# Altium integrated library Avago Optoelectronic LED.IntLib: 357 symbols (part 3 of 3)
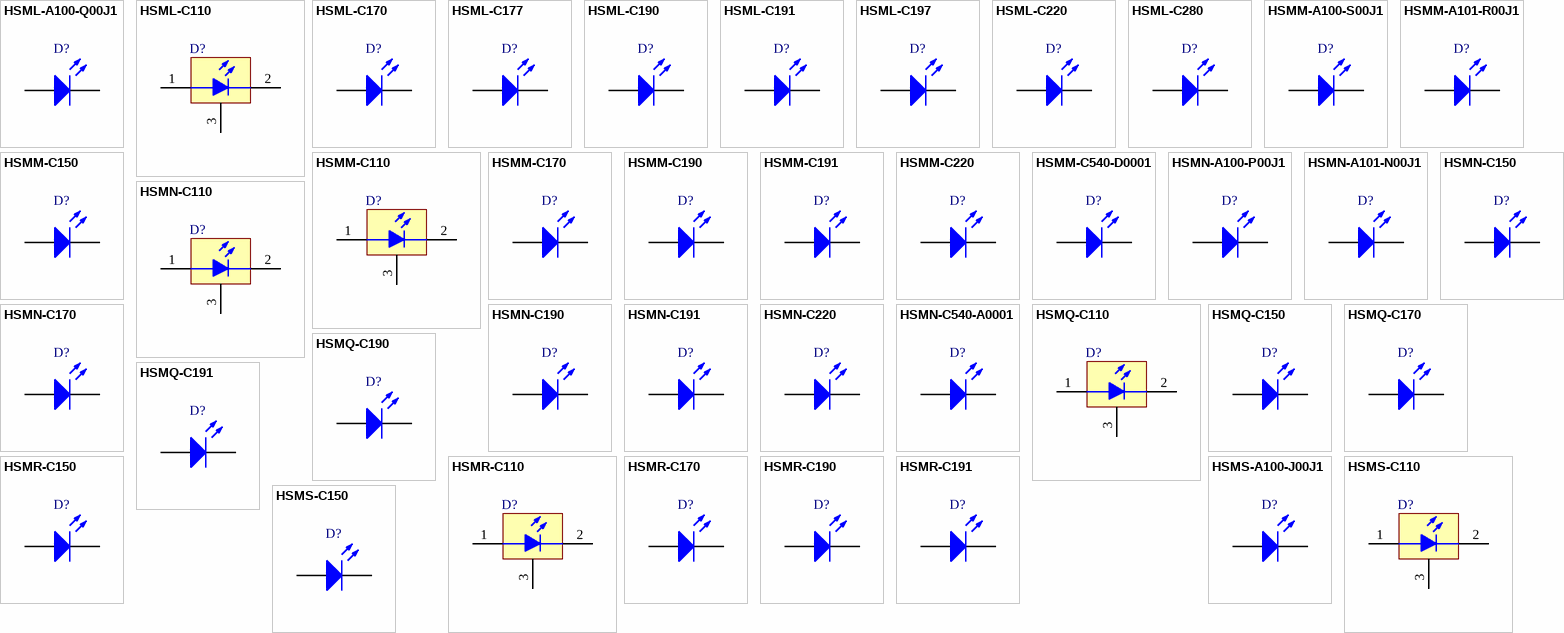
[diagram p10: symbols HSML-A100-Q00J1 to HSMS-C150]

## HSMN-A101-N00J1
designator D?
Surface Mount LED Indicator, Blue; LuminousIntensity: 25mcd (Minimum).; PCB_Layout: Complies with manufacturer's recommendation.
footprint 3.5X2.8X1.9 (SM LED; 2 C-Bend Leads; Body 3.5 x 2.8 x 1.9 mm, inc leads (LxWxH typ))
simulation model Agl_HSMKA100 (Diode)
signal-integrity model LED
pins: 1 A, 2 K

## HSMN-C110
designator D?
High Performance SMT Chip LED, Blue; LuminousIntensity: 10mcd (Minimum).; PCB_Layout: Complies with manufacturer's recommendation.
footprint 3.2X1.0X1.5 (SM Right-Angle Mount LED; 3 Leads; Body 3.2 x 1.0 x 1.5 mm (LxWxH))
simulation model Agl_HSMMC110 (Diode)
pins: 1 A, 2 K, 3 Mount

## HSMN-C150
designator D?
High Performance SMT Chip LED, Blue; LuminousIntensity: 10mcd (Minimum).; PCB_Layout: Complies with manufacturer's recommendation.
footprint 3.2X1.6X1.1 (SM LED; 2 Flat Leads)
simulation model Agl_HSMMC110 (Diode)
signal-integrity model LED
pins: 1 A, 2 K

## HSMN-C170
designator D?
High Performance SMT Chip LED, Blue; LuminousIntensity: 10mcd (Minimum).; PCB_Layout: Complies with manufacturer's recommendation.
footprint 2.0X1.25X0.8 (SM LED; 2 Flat Leads)
simulation model Agl_HSMMC110 (Diode)
signal-integrity model LED
pins: 1 A, 2 K

## HSMN-C190
designator D?
High Performance SMT Chip LED, Blue; LuminousIntensity: 10mcd (Minimum).; PCB_Layout: Complies with manufacturer's recommendation.
footprint 1.6X0.8X0.8 (SM LED; 2 Flat Leads)
simulation model Agl_HSMMC110 (Diode)
signal-integrity model LED
pins: 1 A, 2 K

## HSMN-C191
designator D?
High Performance SMT Chip LED, Blue; LuminousIntensity: 10mcd (Minimum).; PCB_Layout: Complies with manufacturer's recommendation.
footprint 1.6X0.8X0.6 (SM LED; 2 Flat Leads)
simulation model Agl_HSMMC110 (Diode)
signal-integrity model LED
pins: 1 A, 2 K

## HSMN-C220
designator D?
High Performance Chip LED, Blue; LuminousIntensity: 25mcd (Minimum).; PCB_Layout: Complies with manufacturer's recommendation.
footprint 2.0X1.25X1.2 (SM LED; 2 Flat Leads)
simulation model Agl_HSMNC220 (Diode)
signal-integrity model LED
pins: 1 A, 2 K

## HSMN-C540-A0001
designator D?
Top Mount InGaN Blue Oval Lens High Brightness; LuminousIntensity: 26mcd (Minimum).; PCB_Layout: Complies with manufacturer's recommendation.
footprint 2.0X1.25X1.2 (SM LED; 2 Flat Leads)
simulation model Agl_HSMMC540 (Diode)
signal-integrity model LED
pins: 1 A, 2 K

## HSMQ-C110
designator D?
Right Angle SMT Chip LED, Green; LuminousIntensity: 40mcd (Minimum).; PCB_Layout: Complies with manufacturer's recommendation.
footprint 3.2X1.0X1.5 (SM Right-Angle Mount LED; 3 Leads; Body 3.2 x 1.0 x 1.5 mm (LxWxH))
simulation model Agl_HSMQC110 (Diode)
pins: 1 A, 2 K, 3 Mount

## HSMQ-C150
designator D?
SMT Top Mount Chip LED, Green; LuminousIntensity: 40mcd (Minimum).; PCB_Layout: Complies with manufacturer's recommendation.
footprint 3.2X1.6X1.1 (SM LED; 2 Flat Leads)
simulation model Agl_HSMQC110 (Diode)
signal-integrity model LED
pins: 1 A, 2 K

## HSMQ-C170
designator D?
SMT Top Mount Chip LED, Green; LuminousIntensity: 40mcd (Minimum).; PCB_Layout: Complies with manufacturer's recommendation.
footprint 2.0X1.25X0.8 (SM LED; 2 Flat Leads)
simulation model Agl_HSMQC170 (Diode)
signal-integrity model LED
pins: 1 A, 2 K

## HSMQ-C190
designator D?
SMT Top Mount Chip LED, Green; LuminousIntensity: 40mcd (Minimum).; PCB_Layout: Complies with manufacturer's recommendation.
footprint 1.6X0.8X0.8 (SM LED; 2 Flat Leads)
simulation model Agl_HSMQC170 (Diode)
signal-integrity model LED
pins: 1 A, 2 K

## HSMQ-C191
designator D?
Top Mount Low Profile Chip LED, Green; LuminousIntensity: 40mcd (Minimum).; PCB_Layout: Complies with manufacturer's recommendation.
footprint 1.6X0.8X0.6 (SM LED; 2 Flat Leads)
simulation model Agl_HSMQC170 (Diode)
signal-integrity model LED
pins: 1 A, 2 K

## HSMR-C110
designator D?
Right Angle SMT Chip LED, Blue; LuminousIntensity: 16mcd (Minimum).; PCB_Layout: Complies with manufacturer's recommendation.
footprint 3.2X1.0X1.5 (SM Right-Angle Mount LED; 3 Leads; Body 3.2 x 1.0 x 1.5 mm (LxWxH))
simulation model Agl_HSMQC110 (Diode)
pins: 1 A, 2 K, 3 Mount

## HSMR-C150
designator D?
SMT Top Mount Chip LED, Blue; LuminousIntensity: 16mcd (Minimum).; PCB_Layout: Complies with manufacturer's recommendation.
footprint 3.2X1.6X1.1 (SM LED; 2 Flat Leads)
simulation model Agl_HSMQC110 (Diode)
signal-integrity model LED
pins: 1 A, 2 K

## HSMR-C170
designator D?
SMT Top Mount Chip LED, Blue; LuminousIntensity: 16mcd (Minimum).; PCB_Layout: Complies with manufacturer's recommendation.
footprint 2.0X1.25X0.8 (SM LED; 2 Flat Leads)
simulation model Agl_HSMQC170 (Diode)
signal-integrity model LED
pins: 1 A, 2 K

## HSMR-C190
designator D?
SMT Top Mount Chip LED, Blue; LuminousIntensity: 16mcd (Minimum).; PCB_Layout: Complies with manufacturer's recommendation.
footprint 1.6X0.8X0.8 (SM LED; 2 Flat Leads)
simulation model Agl_HSMQC170 (Diode)
signal-integrity model LED
pins: 1 A, 2 K

## HSMR-C191
designator D?
Top Mount Low Profile Chip LED, Blue; LuminousIntensity: 16mcd (Minimum).; PCB_Layout: Complies with manufacturer's recommendation.
footprint 1.6X0.8X0.6 (SM LED; 2 Flat Leads)
simulation model Agl_HSMQC170 (Diode)
signal-integrity model LED
pins: 1 A, 2 K

## HSMS-A100-J00J1
designator D?
Surface Mount LED Indicator, Red; LuminousIntensity: 4mcd (Minimum).; PCB_Layout: Complies with manufacturer's recommendation.
footprint 3.5X2.8X1.9 (SM LED; 2 C-Bend Leads; Body 3.5 x 2.8 x 1.9 mm, inc leads (LxWxH typ))
simulation model Agl_HSMDC110 (Diode)
signal-integrity model LED
pins: 1 A, 2 K

## HSMS-C110
designator D?
Surface Mount Chip LED, Red; LuminousIntensity: 2.5mcd (Minimum).; PCB_Layout: Complies with manufacturer's recommendation.
footprint 3.2X1.0X1.5 (SM Right-Angle Mount LED; 3 Leads; Body 3.2 x 1.0 x 1.5 mm (LxWxH))
simulation model Agl_HSMSC110 (Diode)
pins: 1 A, 2 K, 3 Mount

## HSMS-C150
designator D?
Surface Mount Chip LED, Red; LuminousIntensity: 2.5mcd (Minimum).; PCB_Layout: Complies with manufacturer's recommendation.
footprint 3.2X1.6X1.1 (SM LED; 2 Flat Leads)
simulation model Agl_HSMSC110 (Diode)
signal-integrity model LED
pins: 1 A, 2 K

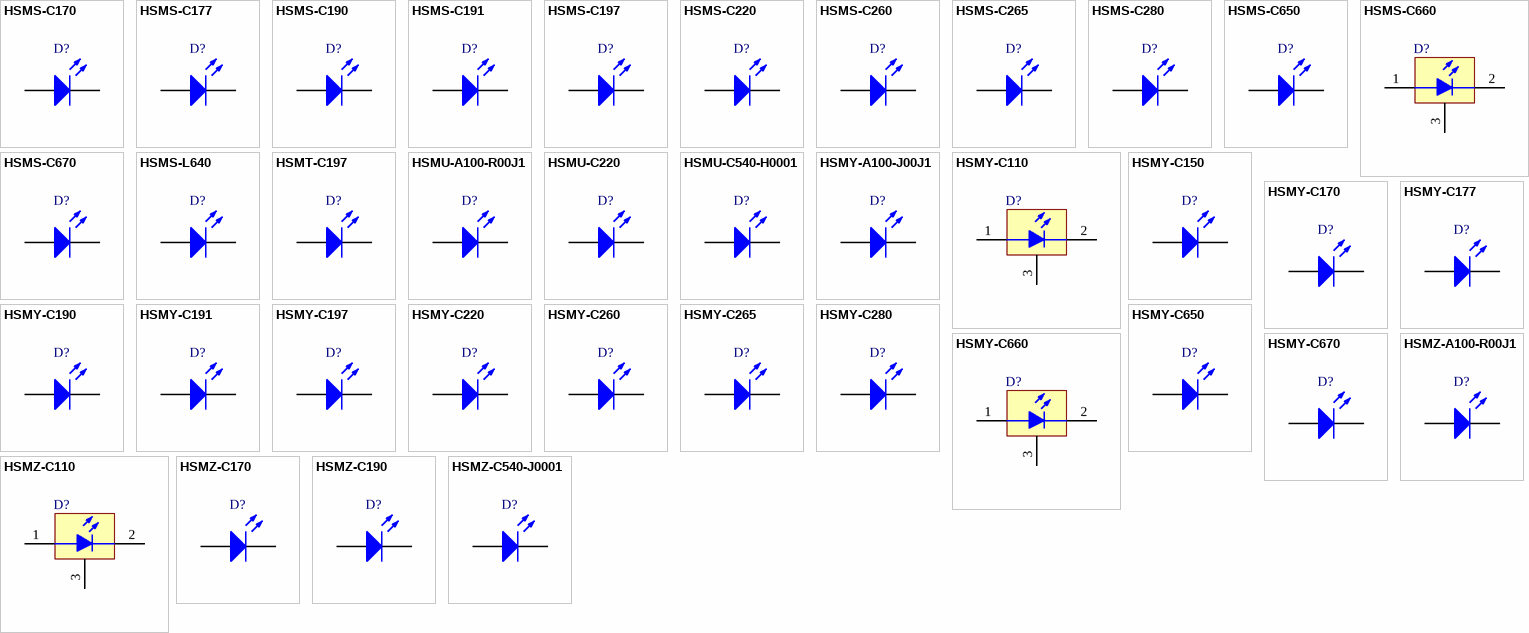
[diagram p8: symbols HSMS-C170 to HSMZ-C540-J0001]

## HSMS-C170
designator D?
Surface Mount Chip LED, Red; LuminousIntensity: 2.5mcd (Minimum).; PCB_Layout: Complies with manufacturer's recommendation.
footprint 2.0X1.25X0.8 (SM LED; 2 Flat Leads)
simulation model Agl_HSMSC110 (Diode)
signal-integrity model LED
pins: 1 A, 2 K

## HSMS-C177
designator D?
Low Profile Chip LED, Red; LuminousIntensity: 2.5mcd (Minimum).; PCB_Layout: Complies with manufacturer's recommendation.
footprint 2.0X1.25X0.4 (SM LED; 2 Flat Leads)
simulation model Agl_HSMSC110 (Diode)
signal-integrity model LED
pins: 1 A, 2 K

## HSMS-C190
designator D?
Surface Mount Chip LED, Red; LuminousIntensity: 2.5mcd (Minimum).; PCB_Layout: Complies with manufacturer's recommendation.
footprint 1.6X0.8X0.8 (SM LED; 2 Flat Leads)
simulation model Agl_HSMSC110 (Diode)
signal-integrity model LED
pins: 1 A, 2 K

## HSMS-C191
designator D?
Low Profile Chip LED, Red; LuminousIntensity: 2.5mcd (Minimum).; PCB_Layout: Complies with manufacturer's recommendation.
footprint 1.6X0.8X0.6 (SM LED; 2 Flat Leads)
simulation model Agl_HSMSC110 (Diode)
signal-integrity model LED
pins: 1 A, 2 K

## HSMS-C197
designator D?
Low Profile Chip LED, Red; LuminousIntensity: 2.5mcd (Minimum).; PCB_Layout: Complies with manufacturer's recommendation.
footprint 1.6X0.8X0.4 (SM LED; 2 Flat Leads)
simulation model Agl_HSMSC110 (Diode)
signal-integrity model LED
pins: 1 A, 2 K

## HSMS-C220
designator D?
High Performance Chip LED, Red; LuminousIntensity: 6.3mcd (Minimum).; PCB_Layout: Complies with manufacturer's recommendation.
footprint 2.0X1.25X1.2 (SM LED; 2 Flat Leads)
simulation model Agl_HSMDC650 (Diode)
signal-integrity model LED
pins: 1 A, 2 K

## HSMS-C260
designator D?
Reverse Mount Chip LED, Red; LuminousIntensity: 2.5mcd (Minimum).; PCB_Layout: Complies with manufacturer's recommendation.; DrillSize: Nominal, Rounded to nearest 0.05mm
footprint 3.4X1.25X1.1 (SM Reverse Mount LED; 2 Flat Leads)
simulation model Agl_HSMSC260 (Diode)
signal-integrity model LED
pins: 1 A, 2 K

## HSMS-C265
designator D?
Reverse Mount Chip LED, Red; LuminousIntensity: 2.5mcd (Minimum).; PCB_Layout: Complies with manufacturer's recommendation.; DrillSize: Nominal, Rounded to nearest 0.05mm
footprint 3.4X1.25X1.1 (SM Reverse Mount LED; 2 Flat Leads)
simulation model Agl_HSMSC265 (Diode)
signal-integrity model LED
pins: 1 A, 2 K

## HSMS-C280
designator D?
Miniature Chip LED, Red; LuminousIntensity: 2.5mcd (Minimum).; PCB_Layout: Complies with manufacturer's recommendation.
footprint 1.0X0.5X0.4 (SM LED; 2 Flat Leads)
simulation model Agl_HSMSC110 (Diode)
signal-integrity model LED
pins: 1 A, 2 K

## HSMS-C650
designator D?
SMT Top Mount Chip LED, Red; LuminousIntensity: 1.6mcd (Minimum).; PCB_Layout: Complies with manufacturer's recommendation.
footprint 3.2X1.6X1.1 (SM LED; 2 Flat Leads)
simulation model Agl_HSMSC650 (Diode)
signal-integrity model LED
pins: 1 A, 2 K

## HSMS-C660
designator D?
Right Angle SMT Chip LED, Red; LuminousIntensity: 1.6mcd (Minimum).; PCB_Layout: Complies with manufacturer's recommendation.
footprint 3.0X1.0X2.0W (SM Right-Angle Mount LED; 3 Leads; Body 3.0 x 1.0 x 2.0 mm (LxWxH))
simulation model Agl_HSMSC650 (Diode)
pins: 1 A, 2 K, 3 Mount

## HSMS-C670
designator D?
SMT Top Mount Chip LED, Red; LuminousIntensity: 1.6mcd (Minimum).; PCB_Layout: Complies with manufacturer's recommendation.
footprint 2.0X1.25X1.1 (SM LED; 2 Flat Leads)
simulation model Agl_HSMSC650 (Diode)
signal-integrity model LED
pins: 1 A, 2 K

## HSMS-L640
designator D?
SMT Top Mount Chip LED, Red; LuminousIntensity: 2.5mcd (Minimum).; PCB_Layout: Complies with manufacturer's recommendation.
footprint 3.0X1.5X1.5 (SM LED; 2 Flat Leads)
simulation model Agl_HSMSC650 (Diode)
signal-integrity model LED
pins: 1 A, 2 K

## HSMT-C197
designator D?
Low Profile Chip LED, Red; LuminousIntensity: 15mcd (Minimum).; PCB_Layout: Complies with manufacturer's recommendation.
footprint 1.6X0.8X0.4 (SM LED; 2 Flat Leads)
simulation model Agl_HSMCC177 (Diode)
signal-integrity model LED
pins: 1 A, 2 K

## HSMU-A100-R00J1
designator D?
Surface Mount LED Indicator, Amber; LuminousIntensity: 100mcd (Minimum).; PCB_Layout: Complies with manufacturer's recommendation.
footprint 3.5X2.8X1.9 (SM LED; 2 C-Bend Leads; Body 3.5 x 2.8 x 1.9 mm, inc leads (LxWxH typ))
simulation model Agl_HSMDC110 (Diode)
signal-integrity model LED
pins: 1 A, 2 K

## HSMU-C220
designator D?
High Performance Chip LED, Amber; LuminousIntensity: 100mcd (Minimum).; PCB_Layout: Complies with manufacturer's recommendation.
footprint 2.0X1.25X1.2 (SM LED; 2 Flat Leads)
simulation model Agl_HSMUC220 (Diode)
signal-integrity model LED
pins: 1 A, 2 K

## HSMU-C540-H0001
designator D?
Top Mount TS AlInGaP Amber Oval Lens High Brightness; LuminousIntensity: 157mcd (Minimum).; PCB_Layout: Complies with manufacturer's recommendation.
footprint 2.0X1.25X1.2 (SM LED; 2 Flat Leads)
simulation model Agl_HSMUC540 (Diode)
signal-integrity model LED
pins: 1 A, 2 K

## HSMY-A100-J00J1
designator D?
Surface Mount LED Indicator, Yellow; LuminousIntensity: 4mcd (Minimum).; PCB_Layout: Complies with manufacturer's recommendation.
footprint 3.5X2.8X1.9 (SM LED; 2 C-Bend Leads; Body 3.5 x 2.8 x 1.9 mm, inc leads (LxWxH typ))
simulation model Agl_HSMDC110 (Diode)
signal-integrity model LED
pins: 1 A, 2 K

## HSMY-C110
designator D?
Surface Mount Chip LED, Yellow; LuminousIntensity: 2.5mcd (Minimum).; PCB_Layout: Complies with manufacturer's recommendation.
footprint 3.2X1.0X1.5 (SM Right-Angle Mount LED; 3 Leads; Body 3.2 x 1.0 x 1.5 mm (LxWxH))
simulation model Agl_HSMYC110 (Diode)
pins: 1 A, 2 K, 3 Mount

## HSMY-C150
designator D?
Surface Mount Chip LED, Yellow; LuminousIntensity: 2.5mcd (Minimum).; PCB_Layout: Complies with manufacturer's recommendation.
footprint 3.2X1.6X1.1 (SM LED; 2 Flat Leads)
simulation model Agl_HSMYC110 (Diode)
signal-integrity model LED
pins: 1 A, 2 K

## HSMY-C170
designator D?
Surface Mount Chip LED, Yellow; LuminousIntensity: 2.5mcd (Minimum).; PCB_Layout: Complies with manufacturer's recommendation.
footprint 2.0X1.25X0.8 (SM LED; 2 Flat Leads)
simulation model Agl_HSMYC110 (Diode)
signal-integrity model LED
pins: 1 A, 2 K

## HSMY-C177
designator D?
Low Profile Chip LED, Yellow; LuminousIntensity: 2.5mcd (Minimum).; PCB_Layout: Complies with manufacturer's recommendation.
footprint 2.0X1.25X0.4 (SM LED; 2 Flat Leads)
simulation model Agl_HSMYC110 (Diode)
signal-integrity model LED
pins: 1 A, 2 K

## HSMY-C190
designator D?
Surface Mount Chip LED, Yellow; LuminousIntensity: 2.5mcd (Minimum).; PCB_Layout: Complies with manufacturer's recommendation.
footprint 1.6X0.8X0.8 (SM LED; 2 Flat Leads)
simulation model Agl_HSMYC110 (Diode)
signal-integrity model LED
pins: 1 A, 2 K

## HSMY-C191
designator D?
Low Profile Chip LED, Yellow; LuminousIntensity: 2.5mcd (Minimum).; PCB_Layout: Complies with manufacturer's recommendation.
footprint 1.6X0.8X0.6 (SM LED; 2 Flat Leads)
simulation model Agl_HSMYC110 (Diode)
signal-integrity model LED
pins: 1 A, 2 K

## HSMY-C197
designator D?
Low Profile Chip LED, Yellow; LuminousIntensity: 2.5mcd (Minimum).; PCB_Layout: Complies with manufacturer's recommendation.
footprint 1.6X0.8X0.4 (SM LED; 2 Flat Leads)
simulation model Agl_HSMYC110 (Diode)
signal-integrity model LED
pins: 1 A, 2 K

## HSMY-C220
designator D?
High Performance Chip LED, Yellow; LuminousIntensity: 6.3mcd (Minimum).; PCB_Layout: Complies with manufacturer's recommendation.
footprint 2.0X1.25X1.2 (SM LED; 2 Flat Leads)
simulation model Agl_HSMYC650 (Diode)
signal-integrity model LED
pins: 1 A, 2 K

## HSMY-C260
designator D?
Reverse Mount Chip LED, Yellow; LuminousIntensity: 2.5mcd (Minimum).; PCB_Layout: Complies with manufacturer's recommendation.; DrillSize: Nominal, Rounded to nearest 0.05mm
footprint 3.4X1.25X1.1 (SM Reverse Mount LED; 2 Flat Leads)
simulation model Agl_HSMYC260 (Diode)
signal-integrity model LED
pins: 1 A, 2 K

## HSMY-C265
designator D?
Reverse Mount Chip LED, Yellow; LuminousIntensity: 2.5mcd (Minimum).; PCB_Layout: Complies with manufacturer's recommendation.; DrillSize: Nominal, Rounded to nearest 0.05mm
footprint 3.4X1.25X1.1 (SM Reverse Mount LED; 2 Flat Leads)
simulation model Agl_HSMYC260 (Diode)
signal-integrity model LED
pins: 1 A, 2 K

## HSMY-C280
designator D?
Miniature Chip LED, Yellow; LuminousIntensity: 2.5mcd (Minimum).; PCB_Layout: Complies with manufacturer's recommendation.
footprint 1.0X0.5X0.4 (SM LED; 2 Flat Leads)
simulation model Agl_HSMYC110 (Diode)
signal-integrity model LED
pins: 1 A, 2 K

## HSMY-C650
designator D?
SMT Top Mount Chip LED, Yellow; LuminousIntensity: 1.6mcd (Minimum).; PCB_Layout: Complies with manufacturer's recommendation.
footprint 3.2X1.6X1.1 (SM LED; 2 Flat Leads)
simulation model Agl_HSMYC650 (Diode)
signal-integrity model LED
pins: 1 A, 2 K

## HSMY-C660
designator D?
Right Angle SMT Chip LED, Yellow; LuminousIntensity: 1.6mcd (Minimum).; PCB_Layout: Complies with manufacturer's recommendation.
footprint 3.0X1.0X2.0W (SM Right-Angle Mount LED; 3 Leads; Body 3.0 x 1.0 x 2.0 mm (LxWxH))
simulation model Agl_HSMYC650 (Diode)
pins: 1 A, 2 K, 3 Mount

## HSMY-C670
designator D?
SMT Top Mount Chip LED, Yellow; LuminousIntensity: 1.6mcd (Minimum).; PCB_Layout: Complies with manufacturer's recommendation.
footprint 2.0X1.25X1.1 (SM LED; 2 Flat Leads)
simulation model Agl_HSMYC650 (Diode)
signal-integrity model LED
pins: 1 A, 2 K

## HSMZ-A100-R00J1
designator D?
Surface Mount LED Indicator, Red; LuminousIntensity: 100mcd (Minimum).; PCB_Layout: Complies with manufacturer's recommendation.
footprint 3.5X2.8X1.9 (SM LED; 2 C-Bend Leads; Body 3.5 x 2.8 x 1.9 mm, inc leads (LxWxH typ))
simulation model Agl_HSMDC110 (Diode)
signal-integrity model LED
pins: 1 A, 2 K

## HSMZ-C110
designator D?
High Performance Chip LED, Red; LuminousIntensity: 40mcd (Minimum).; PCB_Layout: Complies with manufacturer's recommendation.
footprint 3.2X1.0X1.5 (SM Right-Angle Mount LED; 3 Leads; Body 3.2 x 1.0 x 1.5 mm (LxWxH))
simulation model Agl_HSMZC110 (Diode)
pins: 1 A, 2 K, 3 Mount

## HSMZ-C170
designator D?
High Performance Chip LED, Red; LuminousIntensity: 40mcd (Minimum).; PCB_Layout: Complies with manufacturer's recommendation.
footprint 2.0X1.25X0.8 (SM LED; 2 Flat Leads)
simulation model Agl_HSMZC110 (Diode)
signal-integrity model LED
pins: 1 A, 2 K

## HSMZ-C190
designator D?
High Performance Chip LED, Red; LuminousIntensity: 40mcd (Minimum).; PCB_Layout: Complies with manufacturer's recommendation.
footprint 1.6X0.8X0.8 (SM LED; 2 Flat Leads)
simulation model Agl_HSMZC110 (Diode)
signal-integrity model LED
pins: 1 A, 2 K

## HSMZ-C540-J0001
designator D?
Top Mount TS AlInGaP Red Oval Lens High Brightness; LuminousIntensity: 209mcd (Minimum).; PCB_Layout: Complies with manufacturer's recommendation.
footprint 2.0X1.25X1.2 (SM LED; 2 Flat Leads)
simulation model Agl_HSMUC540 (Diode)
signal-integrity model LED
pins: 1 A, 2 K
